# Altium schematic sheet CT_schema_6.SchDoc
size 339 x 183 mm
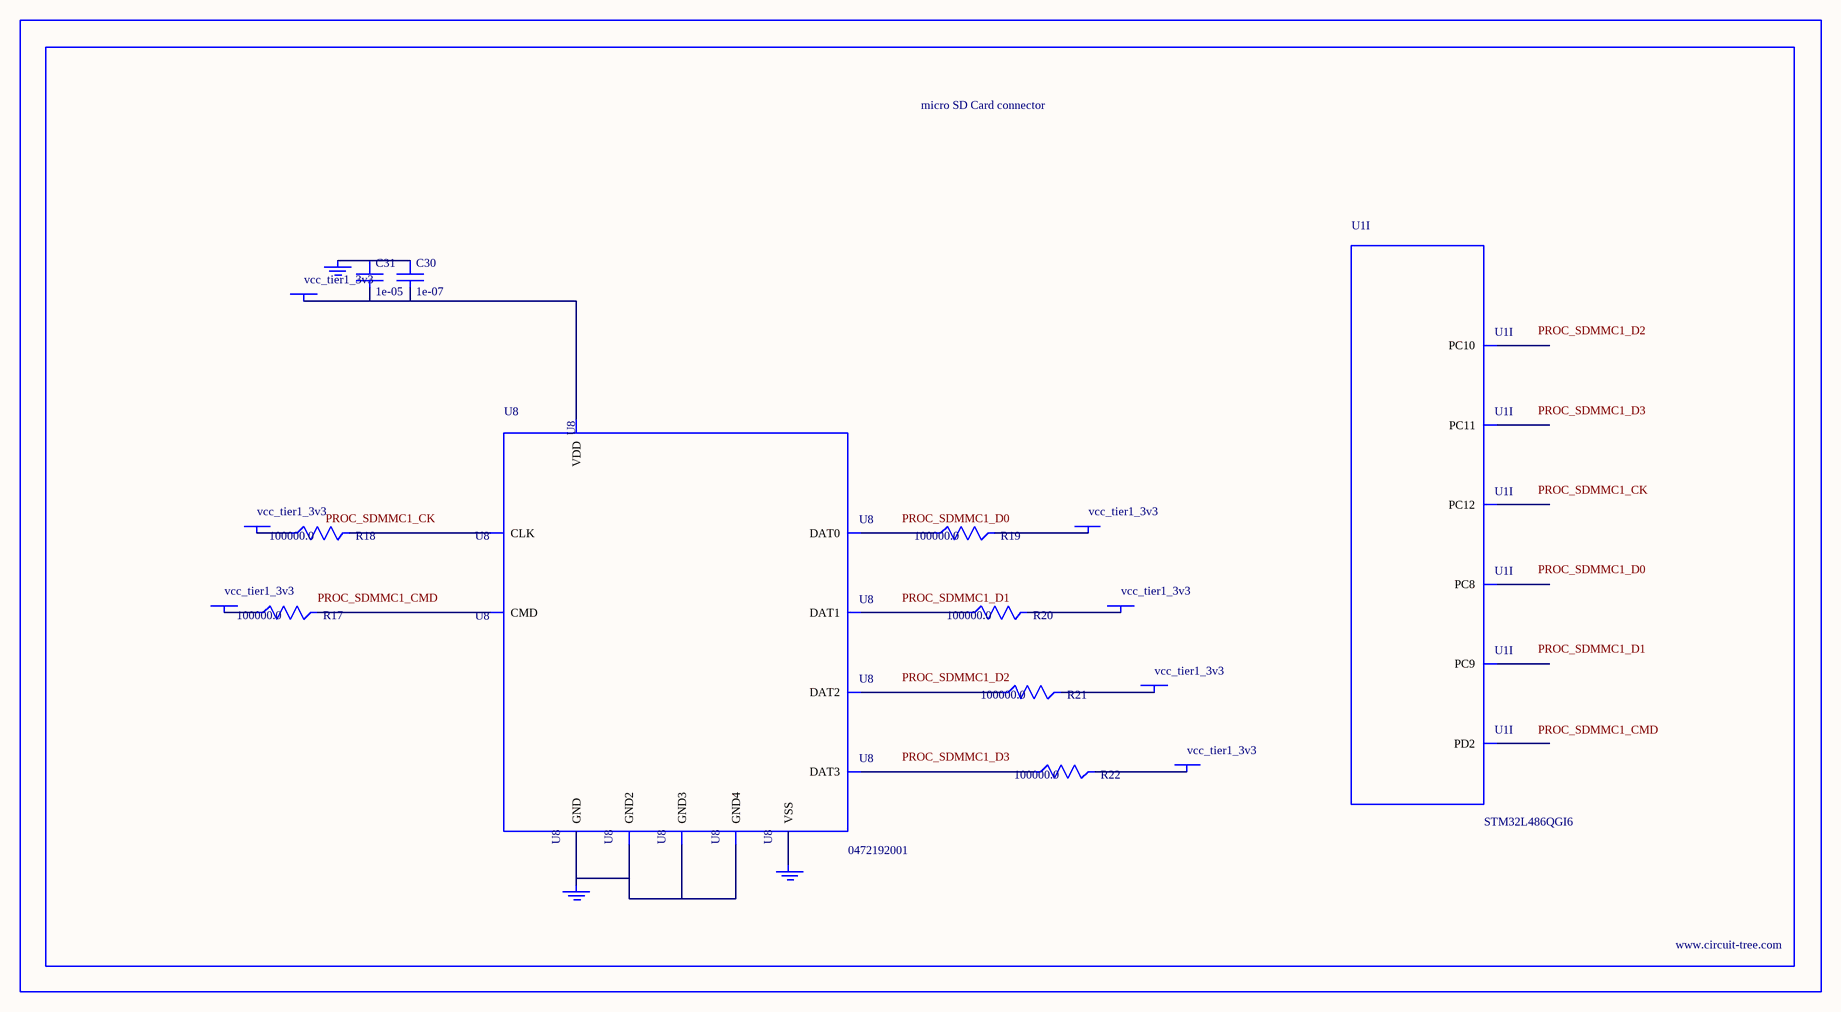
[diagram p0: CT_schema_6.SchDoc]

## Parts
BORDER5  (no value)
C30  1e-07  [C0402]
C31  1e-05  [C0805]
GND_INSTANCE_5_0  (no value)
GND_INSTANCE_5_1  (no value)
GND_INSTANCE_5_2  (no value)
POWER_INSTANCE_5_0  vcc_tier1_3v3
POWER_INSTANCE_5_1  vcc_tier1_3v3
POWER_INSTANCE_5_2  vcc_tier1_3v3
POWER_INSTANCE_5_3  vcc_tier1_3v3
POWER_INSTANCE_5_4  vcc_tier1_3v3
POWER_INSTANCE_5_5  vcc_tier1_3v3
POWER_INSTANCE_5_6  vcc_tier1_3v3
R17  100000.0  [R0603]
R18  100000.0  [R0603]
R19  100000.0  [R0603]
R20  100000.0  [R0603]
R21  100000.0  [R0603]
R22  100000.0  [R0603]
U1  STM32L486QGI6  [UFBGA132]  (part I of 13)
U8  0472192001  [MOLEX_47219-2001]

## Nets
NetC30_1: C30.1 C31.1 GND_INSTANCE_5_0.0(GND)
NetC30_2: C30.2 C31.2 POWER_INSTANCE_5_3.0(PWR) U8.4(VDD)
NetGND_INSTANCE_5_1_0: GND_INSTANCE_5_1.0(GND) U8.6(VSS)
NetGND_INSTANCE_5_2_0: GND_INSTANCE_5_2.0(GND) U8.G1(GND) U8.G2(GND2) U8.G3(GND3) U8.G4(GND4)
NetPOWER_INSTANCE_5_0_0: POWER_INSTANCE_5_0.0(PWR) R21.2
NetPOWER_INSTANCE_5_1_0: POWER_INSTANCE_5_1.0(PWR) R22.2
NetPOWER_INSTANCE_5_2_0: POWER_INSTANCE_5_2.0(PWR) R17.1
NetPOWER_INSTANCE_5_4_0: POWER_INSTANCE_5_4.0(PWR) R18.1
NetPOWER_INSTANCE_5_5_0: POWER_INSTANCE_5_5.0(PWR) R19.2
NetPOWER_INSTANCE_5_6_0: POWER_INSTANCE_5_6.0(PWR) R20.2
NetR17_2: R17.2 U8.3(CMD)
NetR18_2: R18.2 U8.5(CLK)
NetR19_1: R19.1 U8.7(DAT0)
NetR20_1: R20.1 U8.8(DAT1)
NetR21_1: R21.1 U8.1(DAT2)
NetR22_1: R22.1 U8.2(DAT3)

Not connected (* = marked no-connect by the designer): U1 B10(PC12) B11(PC10) C8(PD2) C10(PC11) D12(PC9) E10(PC8)

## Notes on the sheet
- Labels drawn without touching a wire or pin: PROC_SDMMC1_CK, PROC_SDMMC1_CMD, PROC_SDMMC1_D0, PROC_SDMMC1_D1, PROC_SDMMC1_D2, PROC_SDMMC1_D3

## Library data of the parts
BORDER5 = BORDER_PAGE5
C30 = C0402C104K3RACTU
C31 = C0805C106K8RACTU
GND_INSTANCE_5_0-GND_INSTANCE_5_2 = GND
POWER_INSTANCE_5_0-POWER_INSTANCE_5_6 = PWR
R17-R22 = RC0603JR-07100KL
